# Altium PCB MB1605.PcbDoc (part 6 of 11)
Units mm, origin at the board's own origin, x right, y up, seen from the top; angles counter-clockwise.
Board outline 100 x 79.6 mm, 6 copper layers (Top Layer, Signal Layer 1, Signal Layer 2, Signal Layer 3, Signal Layer 4, Bottom Layer), stack 1.549 mm thick; 644 components, 529 nets, 2853 pads, 1462 vias.
Unrouted connection lines stored in the file: 2.
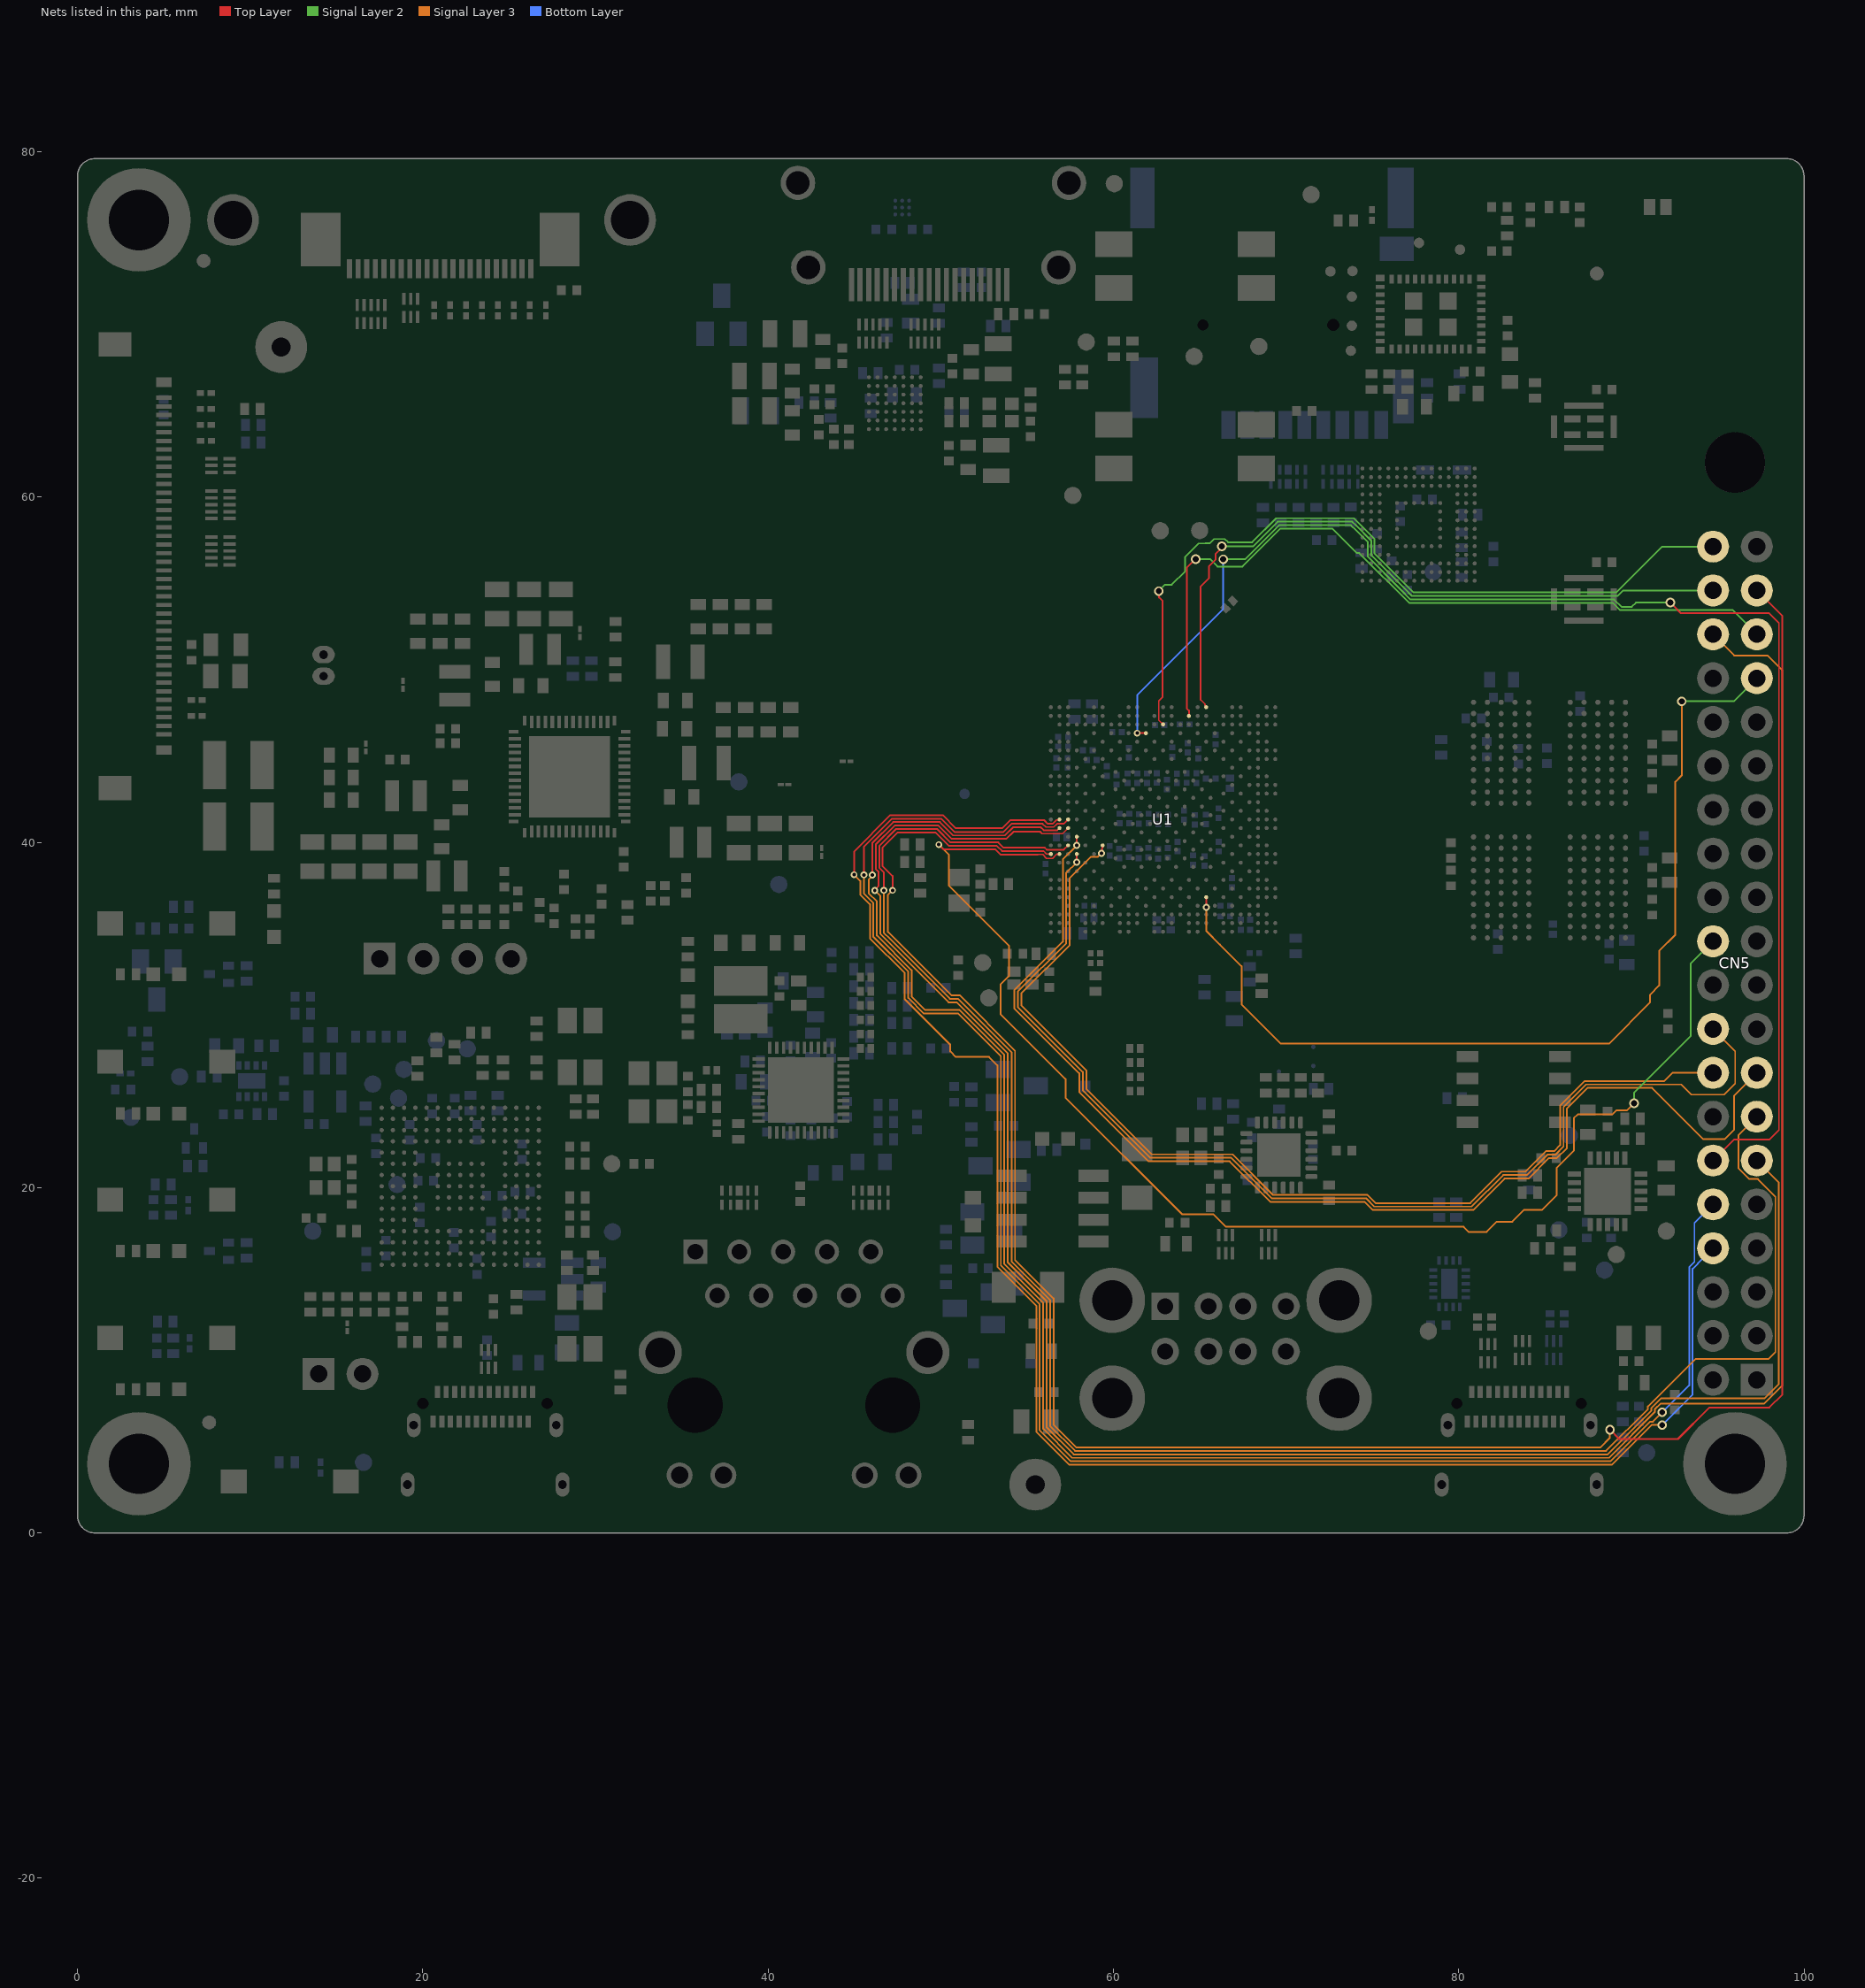
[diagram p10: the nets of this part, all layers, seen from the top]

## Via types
v1: diameter 0.55, hole 0.35, Top Layer to Bottom Layer, 823 vias
v2: diameter 0.4, hole 0.2, Top Layer to Bottom Layer, 235 vias
v3: diameter 0.4, hole 0.2, Top Layer to Bottom Layer, tented both sides, 216 vias
v4: diameter 0.5, hole 0.2, Top Layer to Bottom Layer, 159 vias
v5: diameter 0.25/0.3 (per signal layer), hole 0.1, Top Layer to Signal Layer 1, tented both sides, 29 vias

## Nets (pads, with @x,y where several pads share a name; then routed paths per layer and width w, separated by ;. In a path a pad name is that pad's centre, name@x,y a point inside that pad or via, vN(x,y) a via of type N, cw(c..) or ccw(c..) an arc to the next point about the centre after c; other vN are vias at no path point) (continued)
EXP_GPIO13: CN5.33 U1.AC19 | length 55.8
  Top Layer w0.1: U1.AC19@65.375,36.825 65.378,36.822 65.378,36.243 v3(65.381,36.24)
  Signal Layer 2 w0.1: v1(92.918,48.17) 95.93,48.17 CN5.33@97.27,49.51
  Signal Layer 3 w0.1: v3(65.381,36.24) 65.381,34.864 66.17,34.075 67.425,32.82 67.425,30.606 69.689,28.342 88.7,28.342 91.091,30.732 91.091,31.156 91.093,31.158 91.093,31.19 91.612,31.709 91.612,33.712 92.55,34.65 92.55,43.505 92.918,43.873 v1(92.918,48.17)
EXP_GPIO14: CN5.8 U1.P2 | length 102
  Top Layer w0.09: 56.195,41.075 56.479,41.075 56.702,41.298 56.848,41.298 U1.P2@56.875,41.325
  Top Layer w0.1: v2(44.975,38.125) 44.975,39.464 47.084,41.573 50.112,41.573 50.866,40.82 53.566,40.82 54.04,41.294 55.977,41.294 56.195,41.075
  Signal Layer 3 w0.1: v2(44.975,38.125) 45.332,37.768 45.332,36.976 45.898,36.41 45.898,34.439 47.915,32.423 47.915,30.909 50.554,28.269 50.554,27.888 50.87,27.573 52.793,27.573 53.279,27.086 53.279,15.414 55.531,13.163 55.531,5.865 57.446,3.95 88.874,3.95 91.174,6.25 v1(91.787,6.25)
  Bottom Layer w0.1: v1(91.787,6.25) 93.55,8.013 93.55,15.303 93.854,15.608 93.854,15.614 CN5.8@94.73,16.49
EXP_GPIO15: CN5.10 U1.P3 | length 103.7
  Top Layer w0.09: 55.625,41.075 55.897,41.075 56.087,40.885 56.543,40.885 56.733,41.075 57.125,41.075 U1.P3@57.375,41.325
  Top Layer w0.1: v2(45.541,38.118) 45.541,39.747 47.167,41.373 50.03,41.373 50.8,40.603 53.632,40.603 54.104,41.075 55.625,41.075
  Signal Layer 3 w0.1: v2(45.541,38.118) 45.541,37.05 46.098,36.493 46.098,34.522 48.115,32.505 48.115,30.992 49.021,30.085 51.01,30.085 53.479,27.616 53.479,15.497 55.731,13.246 55.731,5.948 57.529,4.15 88.791,4.15 91.091,6.45 91.25,6.45 v1(91.787,6.987)
  Bottom Layer w0.1: v1(91.787,6.987) 93.35,8.55 93.35,15.386 93.654,15.69 93.654,17.954 CN5.10@94.73,19.03
EXP_GPIO16: CN5.36 U1.R2 | length 143
  Top Layer w0.09: 56.166,40.7 56.747,40.7 56.872,40.825 U1.R2@56.875,40.825
  Top Layer w0.1: v2(46.042,38.109) 46.036,38.115 46.036,39.96 47.25,41.173 49.947,41.173 50.718,40.403 53.715,40.403 54.187,40.875 55.782,40.875 55.957,40.7 56.166,40.7
  Signal Layer 3 w0.1: v2(46.042,38.109) 46.042,38.044 45.827,37.829 45.827,37.046 46.298,36.575 46.298,34.605 48.315,32.588 48.315,31.075 49.104,30.285 51.093,30.285 53.679,27.698 53.679,15.58 55.931,13.329 55.931,6.031 57.612,4.35 88.708,4.35 91.362,7.004 91.362,7.164 91.699,7.5 97.703,7.5 98.745,8.542 98.745,49.967 97.887,50.825 95.955,50.825 CN5.36@94.73,52.05
EXP_GPIO17: CN5.11 U1.R3 | length 108.9
  Top Layer w0.09: 56.655,40.505 57.055,40.505 U1.R3@57.375,40.825
  Top Layer w0.1: v2(46.177,37.215) 46.177,37.263 46.401,37.486 46.401,38.287 46.236,38.452 46.236,39.877 47.333,40.973 49.864,40.973 50.635,40.203 53.798,40.203 54.215,40.62 55.746,40.62 55.861,40.505 56.655,40.505
  Signal Layer 3 w0.1: v2(46.177,37.215) 46.498,36.894 46.498,34.688 50.189,30.997 50.445,30.74 50.92,30.74 53.879,27.781 53.879,15.663 56.131,13.411 56.131,6.114 57.695,4.55 88.625,4.55 91.162,7.087 91.162,7.246 91.711,7.795 97.715,7.795 98.545,8.625 98.545,20.295 CN5.11@97.27,21.57
EXP_GPIO18: CN5.12 U1.D12 | length 82.6
  Top Layer w0.1: v3(61.375,46.325) U1.D12@61.875,46.325 ; v1(92.264,53.886) 92.874,53.276 97.985,53.276 98.55,52.711 98.55,23.343 97.986,22.778 95.939,22.778 CN5.12@94.73,21.57
  Signal Layer 2 w0.1: v1(66.362,56.397) 67.618,56.397 69.595,58.374 73.752,58.374 74.056,58.07 74.74,57.386 74.74,56.543 76.578,54.705 77.213,54.07 89.003,54.07 89.428,53.645 90.025,53.645 90.266,53.886 v1(92.264,53.886)
  Bottom Layer w0.1: v3(61.375,46.325) 61.375,48.53 66.362,53.518 v1(66.362,56.397)
EXP_GPIO19: CN5.35 U1.B17 | length 45.5
  Top Layer w0.1: U1.B17@64.375,47.325 64.375,47.638 64.251,47.763 64.251,55.893 v1(64.762,56.404)
  Signal Layer 2 w0.1: v1(64.762,56.404) 65.6,56.404 66.032,55.972 67.476,55.972 69.678,58.174 72.675,58.174 74.094,56.755 74.245,56.755 77.133,53.867 88.923,53.867 89.345,53.445 95.875,53.445 CN5.35@97.27,52.05
EXP_GPIO20: CN5.38 U1.A19 | length 41.4
  Top Layer w0.09: 65.051,48.575 65.051,48.257 65.305,48.003 65.305,47.933 65.375,47.863 U1.A19@65.375,47.825
  Top Layer w0.1: 65.051,48.575 65.051,54.817 65.525,55.291 65.525,55.975 65.915,56.365 65.915,56.697 66.28,57.062 v1(66.28,57.145)
  Signal Layer 2 w0.1: v1(66.28,57.145) 68.083,57.145 69.512,58.574 73.835,58.574 74.056,58.353 74.93,57.479 74.93,56.636 76.861,54.705 77.295,54.27 89.203,54.27 89.523,54.59 CN5.38@94.73,54.59
EXP_GPIO21: CN5.40 U1.C14 | length 45.9
  Top Layer w0.09: 62.85,48.575 62.85,48.421 62.625,48.196 62.625,47.075 U1.C14@62.875,46.825
  Top Layer w0.1: v1(62.625,54.55) 62.649,54.526 62.649,54.184 62.85,53.983 62.85,48.575
  Signal Layer 2 w0.1: v1(62.625,54.55) 62.996,54.921 63.379,54.921 64.161,55.703 64.161,56.543 64.929,57.311 65.327,57.311 65.334,57.318 65.57,57.318 65.822,57.57 66.456,57.57 66.64,57.386 68.041,57.386 69.429,58.774 73.918,58.774 74.056,58.636 75.12,57.572 75.12,56.728 77.143,54.705 77.378,54.47 89.12,54.47 91.78,57.13 CN5.40@94.73,57.13
EXP_GPIO22: CN5.15 U1.T4 | length 68.2
  Top Layer w0.09: v3(57.875,39.825) U1.T4@57.875,40.325
  Signal Layer 3 w0.1: v3(57.875,39.825) 57.075,39.025 57.075,34.245 54.259,31.429 54.259,30.387 58.026,26.62 58.026,25.55 62.048,21.527 66.735,21.527 69.083,19.179 74.547,19.179 75.022,18.705 80.834,18.705 82.658,20.529 84.036,20.529 85.221,21.714 85.687,21.714 86.271,22.298 86.271,24.587 87.459,25.775 91.199,25.775 94.164,22.81 95.404,22.81 95.95,23.356 95.95,25.33 CN5.15@97.27,26.65
EXP_GPIO23: CN5.16 U1.U7 | length 61.3
  Top Layer w0.1: v3@59.3,39.367 59.316,39.465 U1.U7@59.375,39.825
  Signal Layer 3 w0.1: v3@59.3,39.367 59.095,39.162 58.701,39.162 57.689,38.15 57.68,38.15 57.465,37.935 57.465,34.058 54.659,31.252 54.659,30.552 58.426,26.786 58.426,25.715 62.214,21.927 66.901,21.927 69.249,19.579 74.713,19.579 75.187,19.105 80.668,19.105 82.492,20.929 83.87,20.929 85.055,22.114 85.522,22.114 85.871,22.464 85.871,24.752 87.293,26.175 91.906,26.175 92.381,26.65 CN5.16@94.73,26.65
  other v3: 59.305,39.367
EXP_GPIO24: CN5.18 U1.V4 | length 65.7
  Top Layer w0.09: v3(57.875,38.85) U1.V4@57.875,39.325
  Signal Layer 3 w0.1: v3(57.875,38.85) 57.265,38.24 57.265,34.152 54.459,31.346 54.459,30.47 58.226,26.703 58.226,25.633 62.131,21.727 66.818,21.727 69.166,19.379 74.63,19.379 75.104,18.905 80.751,18.905 82.575,20.729 83.953,20.729 85.138,21.914 85.604,21.914 86.071,22.381 86.071,24.67 87.376,25.975 92.891,25.975 93.478,25.388 95.363,25.388 96.013,26.037 96.013,27.908 CN5.18@94.73,29.19
EXP_GPIO25: CN5.22 U1.V2 | length 78.1
  Top Layer w0.09: 55.625,39.294 55.905,39.294 56.123,39.075 56.479,39.075 56.715,39.311 56.861,39.311 U1.V2@56.875,39.325
  Top Layer w0.1: v2(49.889,39.866) 50.162,39.594 53.164,39.594 53.464,39.294 55.625,39.294
  Signal Layer 2 w0.1: v1(90.163,24.887) 90.163,25.506 93.435,28.778 93.435,32.975 CN5.22@94.73,34.27
  Signal Layer 3 w0.1: v2(49.889,39.866) 50.464,39.292 50.464,37.499 53.947,34.015 53.947,32.248 53.459,31.76 53.459,30.055 57.226,26.289 57.226,25.218 63.996,18.448 65.802,18.448 66.521,17.729 80.283,17.729 80.572,17.44 81.619,17.44 82.202,18.023 83.102,18.023 83.793,18.714 84.835,18.714 85.668,19.546 85.668,21.129 86.671,22.132 86.671,24.024 86.891,24.244 88.901,24.244 89.137,24.481 89.756,24.481 v1(90.163,24.887)
EXP_GPIO26: CN5.37 U1.V1 | length 140.6
  Top Layer w0.09: 55.625,39.494 55.959,39.494 56.128,39.325 U1.V1@56.375,39.325
  Top Layer w0.1: v2(47.204,37.221) 47.204,38.049 46.636,38.617 46.636,39.705 47.505,40.573 49.698,40.573 50.478,39.794 53.247,39.794 53.546,39.494 55.625,39.494 ; v1(88.759,5.983) v1(88.759,5.983) 89.299,5.44 92.694,5.44 94.524,7.27 97.995,7.27 98.75,8.025 98.75,53.11 CN5.37@97.27,54.59
  Signal Layer 3 w0.1: v2(47.204,37.221) 46.94,36.958 46.94,34.811 50.611,31.14 51.086,31.14 54.3,27.926 54.3,15.808 56.531,13.577 56.531,6.28 57.86,4.95 88.193,4.95 88.759,5.516 v1(88.759,5.983)
EXP_GPIO27: CN5.13 U1.U3 | length 110.3
  Top Layer w0.09: 56.264,39.575 56.271,39.575 57.125,39.575 U1.U3@57.375,39.825
  Top Layer w0.1: v2(46.698,37.221) 46.698,38.272 46.436,38.535 46.436,39.794 47.415,40.773 49.781,40.773 50.561,39.994 53.329,39.994 53.629,39.694 56.021,39.694 56.139,39.575 56.264,39.575
  Signal Layer 3 w0.1: v2(46.698,37.221) 46.698,34.77 47.075,34.394 50.528,30.94 51.003,30.94 54.1,27.844 54.1,15.725 56.331,13.494 56.331,6.197 57.777,4.75 88.543,4.75 90.963,7.17 90.963,7.329 93.707,10.073 97.933,10.073 98.345,10.485 98.345,19.475 97.325,20.495 96.825,20.495 96.195,21.125 96.195,23.035 CN5.13@97.27,24.11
